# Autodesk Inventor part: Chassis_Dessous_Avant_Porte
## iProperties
Created: 2009-02
Part Number: Chassis_Dessous_Avant_Porte
Document SubType Name: Sheet Metal
Designer: claivier
Author: claivier
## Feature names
1. Extrusion1
2. Couper2
3. Couper3
